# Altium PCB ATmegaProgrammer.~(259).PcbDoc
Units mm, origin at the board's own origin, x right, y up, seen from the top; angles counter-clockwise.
Board outline 55.37 x 50.8 mm, 2 copper layers (Top Layer, Bottom Layer); 13 components, 10 nets, 72 pads, 0 vias.
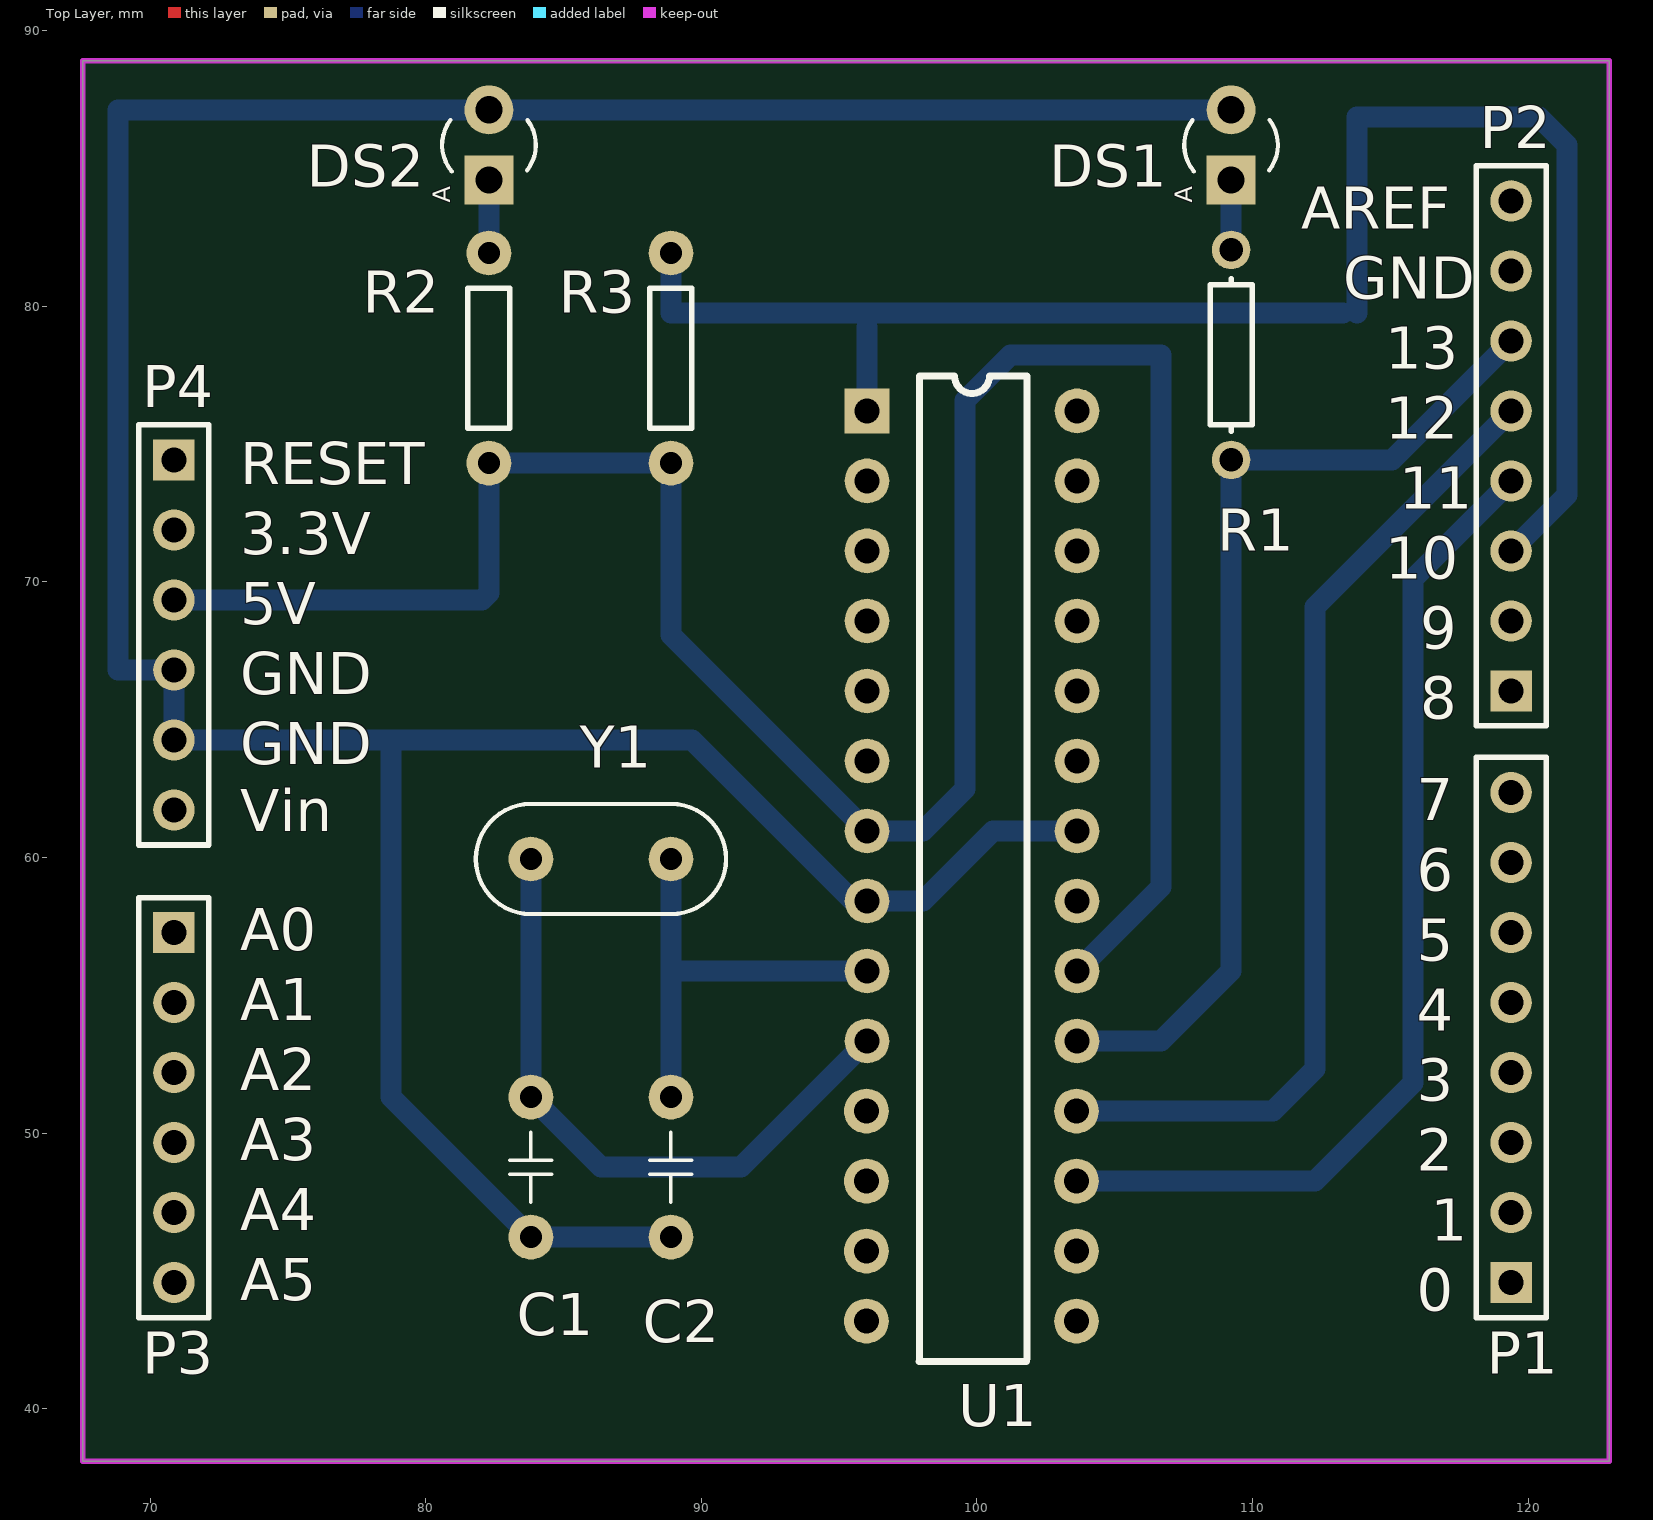
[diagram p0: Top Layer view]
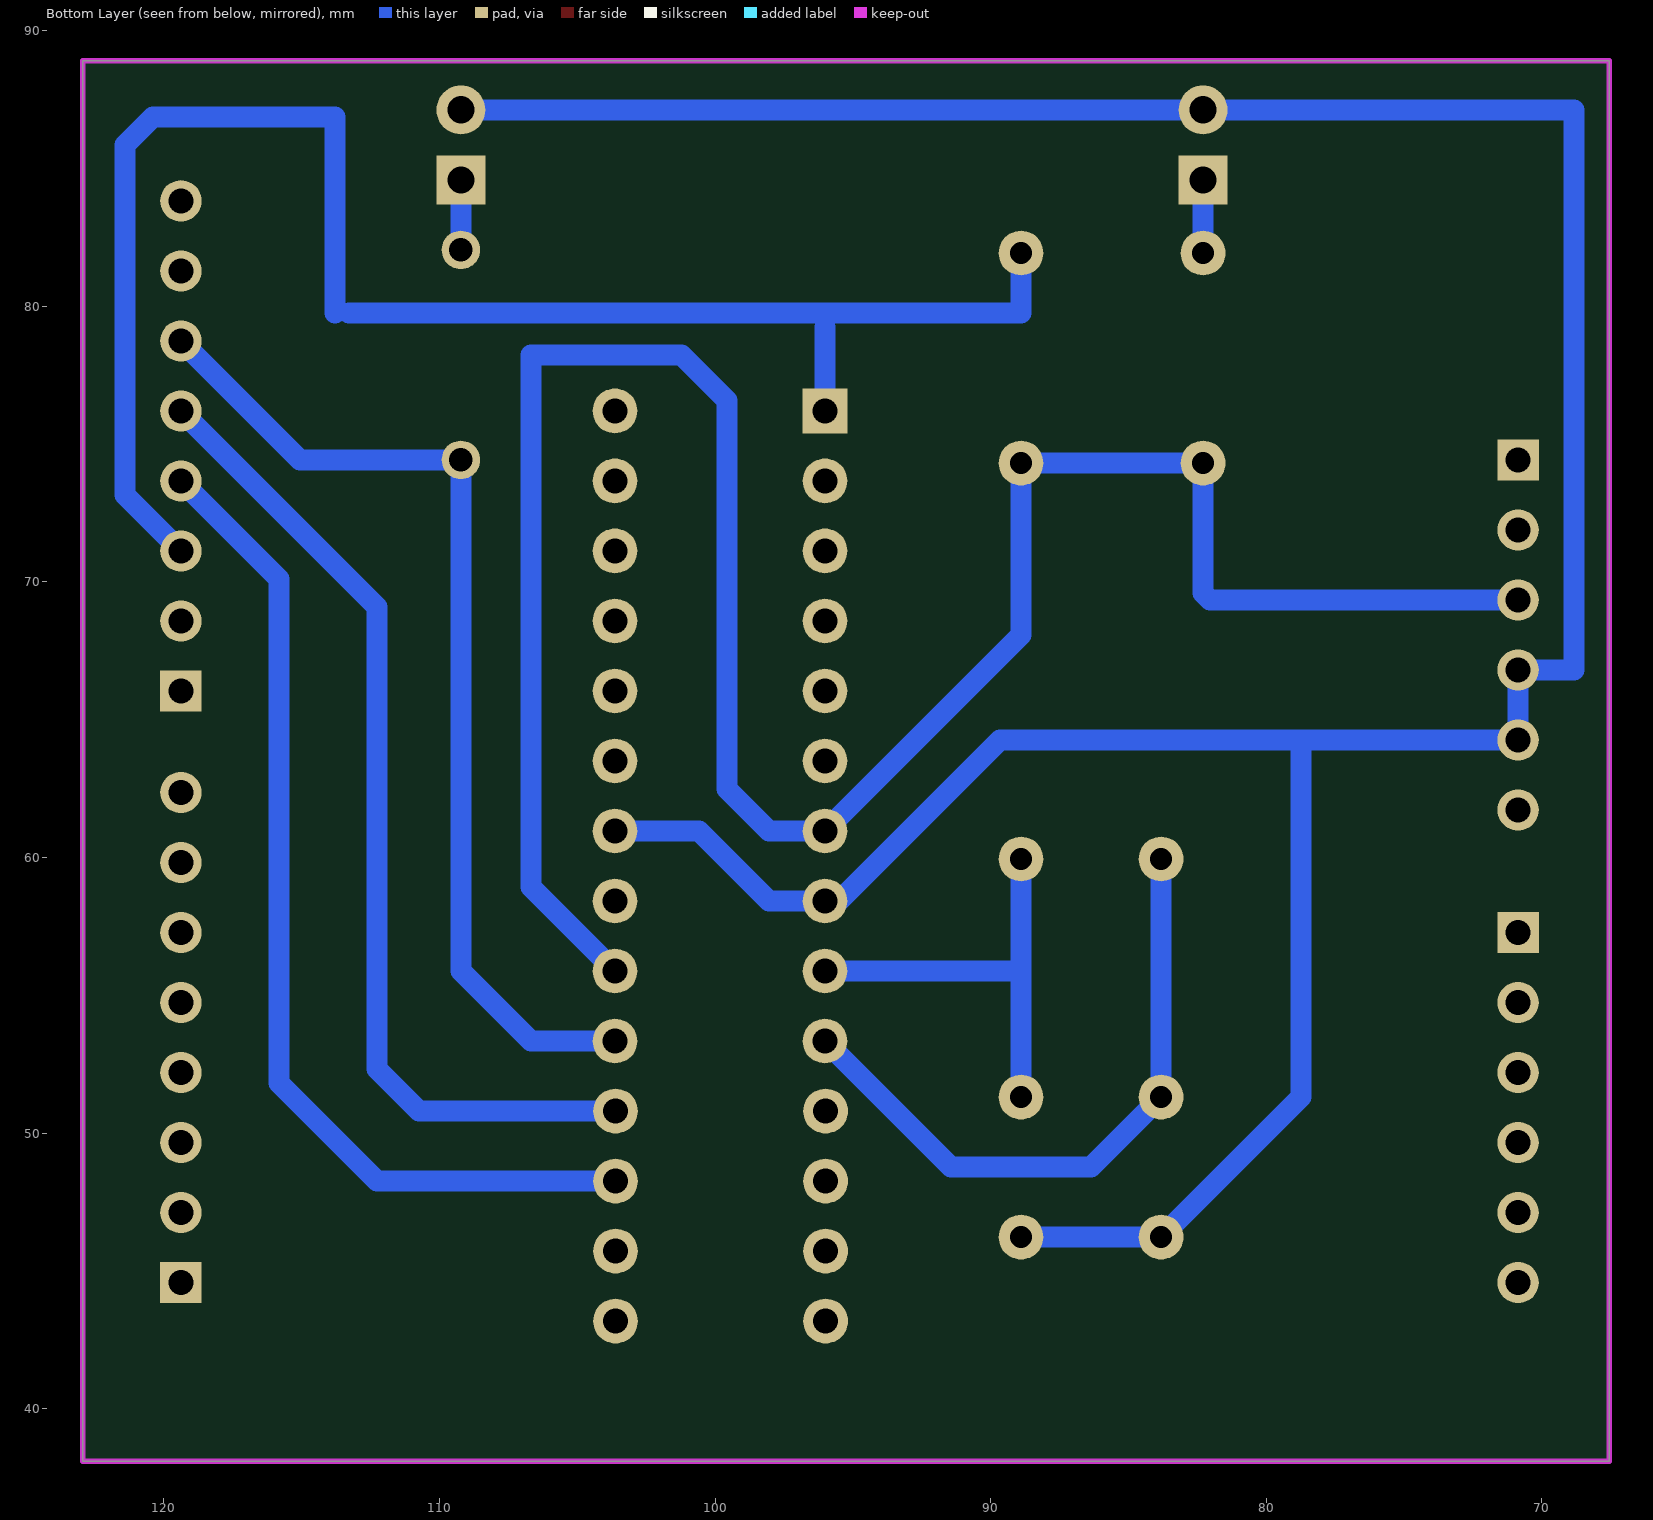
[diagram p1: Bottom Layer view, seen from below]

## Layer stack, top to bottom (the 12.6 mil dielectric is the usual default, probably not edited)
Top Layer: signal copper 0.0356
Dielectric: dielectric 0.32, FR-4, Dk 4.8
Bottom Layer: signal copper 0.0356

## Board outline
67.564,38.1 67.564,88.9 122.936,88.9 122.936,38.1

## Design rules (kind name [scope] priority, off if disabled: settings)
Clearance [All] p1: gap=0.254
PolygonConnect [All] p1: connectstyle=Relief reliefconductorwidth=0.254 reliefentries=4 polygonreliefangle="90 Angle"
RoutingLayers [All] p1: top layer_v5=FALSE bottom layer_v5=TRUE
RoutingVias [All] p1: holewidth=0.711 width=1.27 viastyle="Through Hole" minholewidth=0.711 minwidth=1.27 maxholewidth=0.711 maxwidth=1.27
SilkscreenOverComponentPads [All] p1: minsilkscreentomaskgap=0.254
SolderMaskExpansion [All] p1: expansion=0.102
Width VCC [All] p1: maxlimit=1.016 minlimit=0.508 preferedwidth=0.762
Width GND [InNet('GND')] p2: maxlimit=1.016 minlimit=0.508 preferedwidth=0.762
Width [All] p3: maxlimit=1.016 minlimit=0.254 preferedwidth=0.762
26 further rules are at their usual default settings.

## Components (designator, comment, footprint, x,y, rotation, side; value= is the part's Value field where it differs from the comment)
C1 "20pF" C200 83.82,48.768 r180 top
C2 "20pF" C200 88.9,48.768 r180 top
DS1 "LED" LED-3mm_G 109.22,85.852 r90 top
DS2 "LED" LED-3mm_G 82.296,85.852 r90 top
P1 "Header 8" HDR1X8 119.38,44.577 r90 top
P2 "Header 8" HDR1X8 119.38,66.04 r90 top
P3 "Header 6" HDR1X6 70.866,57.277 r270 top
P4 "Header 6" HDR1X6 70.866,74.422 r270 top
R1 "Res1" AXIAL-0.3#1 109.22,78.232 r270 top
R2 "220" AXIAL-0.3#2 82.296,78.119 r270 top
R3 "10k" AXIAL-0.3#2 88.9,78.119 r270 top
U1 "ATmega328" DIP-28 96.012,76.2 r270 top
Y1 "16MHz" XTAL4-8 86.36,59.944 r180 top

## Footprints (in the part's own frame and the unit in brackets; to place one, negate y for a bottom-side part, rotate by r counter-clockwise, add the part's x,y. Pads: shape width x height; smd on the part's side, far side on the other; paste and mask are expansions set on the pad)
AXIAL-0.3#1 [mm] "Axial Device, Thru-Hole; 2 Leads; 0.3 in Pin Spacing"
  round 1.4 hole 0.85: 1(-3.81,0) 2(3.81,0)
  silkscreen extent -2.77,-0.76 2.77,0.76
AXIAL-0.3#2 [mm] "0.3\" Resistor; 2 Leads"
  round 1.626 hole 0.8: 1(-3.81,0) 2(3.81,0)
  silkscreen extent -2.54,-0.76 2.54,0.76, body extent -4.1,-1 4.19,1, height 2.19
C200 [mil] "鹅溅筿甧竟"
  round 64 hole 31.5: 1(0,100) 2(0,-100)
  silkscreen extent -30,-50 30,50, body extent -41,-136 39,135, height 354
DIP-28 [mil]
  rect 64x64 hole 35.43: 1(0,0)
  round 64 hole 35.43: 2(100,0) 3(200,0) 4(300,0) 5(400,0) 6(500,0) 7(600,0) 8(700,0) 9(800,0) 10(900,0) 11(1000,-0.79) 12(1100,-0.79) 13(1200,-0.79) 14(1300,-0.79) 15(1300,299.21) 16(1200,299.21) 17(1100,299.21) 18(1000,299.21) 19(900,300) 20(800,300) 21(700,300) 22(600,300) 23(500,300) 24(400,300) 25(300,300) 26(200,300) 27(100,300) 28(0,300)
  silkscreen extent -50,74 1358,228, body extent -53,-5 1358,304, height 209
HDR1X6 [mm] "Connector; Header; 6 Position"
  rect 1.5x1.5 hole 0.9: 1(0,0)
  round 1.5 hole 0.9: 2(2.54,0) 3(5.08,0) 4(7.62,0) 5(10.16,0) 6(12.7,0)
  silkscreen extent -1.27,-1.27 13.97,1.27
HDR1X8 [mm] "Connector; Header; 8 Position"
  rect 1.5x1.5 hole 0.9: 1(0,0)
  round 1.5 hole 0.9: 2(2.54,0) 3(5.08,0) 4(7.62,0) 5(10.16,0) 6(12.7,0) 7(15.24,0) 8(17.78,0)
  silkscreen extent -1.27,-1.27 19.05,1.27
LED-3mm_G [mil] "3mm LED_Green"
  rect 70x70 hole 39: 1(-50,0)
  round 70 hole 39: 2(50,0)
  silkscreen extent -38,-67 35,67, body extent -66,-68 67,66, height 181
XTAL4-8 [mil]
  round 64 hole 31.5: 1(-100,0) 2(100,0)
  silkscreen extent -179,-79 179,79, body extent -178,-80 192,79, height 157

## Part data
C1 C2: library part Cap, "Capacitor"
DS1 DS2: "Typical INFRARED GaAs LED"
P1 P2: "Header, 8-Pin"
P3 P4: "Header, 6-Pin"
R1: "Resistor"
R2 R3: library part Res, "Resistor"
U1: "Arduino"
Y1: library part XTAL, "Crystal Oscillator"

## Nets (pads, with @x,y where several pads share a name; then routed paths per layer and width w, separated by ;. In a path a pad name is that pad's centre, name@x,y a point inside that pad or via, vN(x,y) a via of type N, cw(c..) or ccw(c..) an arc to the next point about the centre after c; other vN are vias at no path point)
GND: C1.1 C2.1 DS1.2 DS2.2 P4.4 P4.5 U1.8 U1.22 | length 126.7
  Bottom Layer w0.762: C2.1 C1.1 78.74,51.308 78.74,64.262 ; U1.8@95.758,58.166 89.662,64.262 78.74,64.262 ; U1.8 98.044,58.42 100.584,60.96 U1.22 U1.22@103.737,60.96 ; DS1.2 DS2.2 68.834,87.122 68.834,66.802 P4.4 P4.5 78.74,64.262
MISO: P2.5 U1.18 | length 36.1
  Bottom Layer w0.762: U1.18 110.744,50.8 112.268,52.324 112.268,69.088 P2.5
MOSI: P2.4 U1.17 | length 37
  Bottom Layer w0.762: U1.17 112.268,48.26 115.824,51.816 115.824,70.104 P2.4
NetC1_2: C1.2 U1.10 Y1.2 | length 23.8
  Bottom Layer w0.762: Y1.2 C1.2 86.36,48.768 91.44,48.768 U1.10
NetC2_2: C2.2 U1.9 Y1.1 | length 15.7
  Bottom Layer w0.762: C2.2 88.9,55.88 ; Y1.1 88.9,55.88 ; U1.9 88.9,55.88
NetDS1_1: DS1.1 R1.1 | length 2.5
  Bottom Layer w0.762: R1.1 DS1.1
NetDS2_1: DS2.1 R2.1 | length 2.7
  Bottom Layer w0.762: R2.1 DS2.1
RESET: P2.3 R3.1 U1.1 | length 60.3
  Bottom Layer w0.762: R3.1 88.9,79.756 113.284,79.756 ; U1.1 96.012,79.248 ; 113.792,79.756 113.792,86.868 120.396,86.868 121.412,85.852 121.412,73.152 P2.3
SCK: P2.6 R1.2 U1.19 | length 37.1
  Bottom Layer w0.762: U1.19 106.68,53.34 109.22,55.88 R1.2 115.062,74.422 P2.6
VCC: P4.3 R2.2 R3.2 U1.7 U1.20 | length 88.8
  Bottom Layer w0.762: P4.3 82.042,69.342 82.296,69.596 R2.2 R3.2 88.9,68.072 U1.7 98.044,60.96 99.568,62.484 99.568,76.581 101.219,78.232 106.68,78.232 106.68,58.928 U1.20
pads on no net: P1.1 P1.2 P1.3 P1.4 P1.5 P1.6 P1.7 P1.8 P2.1 P2.2 P2.7 P2.8 P3.1 P3.2 P3.3 P3.4 P3.5 P3.6 P4.1 P4.2 P4.6 U1.2 U1.3 U1.4 U1.5 U1.6 U1.11 U1.12 U1.13 U1.14 U1.15 U1.16 U1.21 U1.23 U1.24 U1.25 U1.26 U1.27 U1.28

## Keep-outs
Keep-Out Layer:
  the board outline again, w0.2

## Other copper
Bottom Layer:
  text "AtProgrammer" at 131.064,91.44 h1.52 r90

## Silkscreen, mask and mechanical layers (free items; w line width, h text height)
Top Overlay:
  lines w0.2: 0,0 0,5.08 ; 0.508,0 0.889,0 ; 1.397,0 4.953,0 ; 69.596,43.307 69.596,43.516
  text "AREF" at 111.76,82.804 h1.52
  text "GND" at 113.284,80.264 h1.52
  text "13" at 114.807,77.724 h1.52
  text "12" at 114.807,75.184 h1.52
  text "RESET" at 73.28,73.533 h1.52
  text "11" at 115.315,72.644 h1.52
  text "3.3V" at 73.28,70.993 h1.52
  text "10" at 114.807,70.104 h1.52
  text "5V" at 73.28,68.453 h1.52
  text "9" at 116.077,67.564 h1.52
  text "GND" at 73.28,65.913 h1.52
  text "8" at 116.077,65.024 h1.52
  text "GND" at 73.28,63.373 h1.52
  text "7" at 115.95,61.341 h1.52
  text "Vin" at 73.28,60.96 h1.52
  text "6" at 115.95,58.801 h1.52
  text "A0" at 73.28,56.642 h1.52
  text "5" at 115.95,56.261 h1.52
  text "A1" at 73.28,54.102 h1.52
  text "4" at 115.95,53.721 h1.52
  text "A2" at 73.28,51.562 h1.52
  text "3" at 115.95,51.181 h1.52
  text "A3" at 73.28,49.022 h1.52
  text "2" at 115.95,48.641 h1.52
  text "A4" at 73.28,46.482 h1.52
  text "1" at 116.457,46.101 h1.52
  text "A5" at 73.28,43.942 h1.52
  text "0" at 115.95,43.561 h1.52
